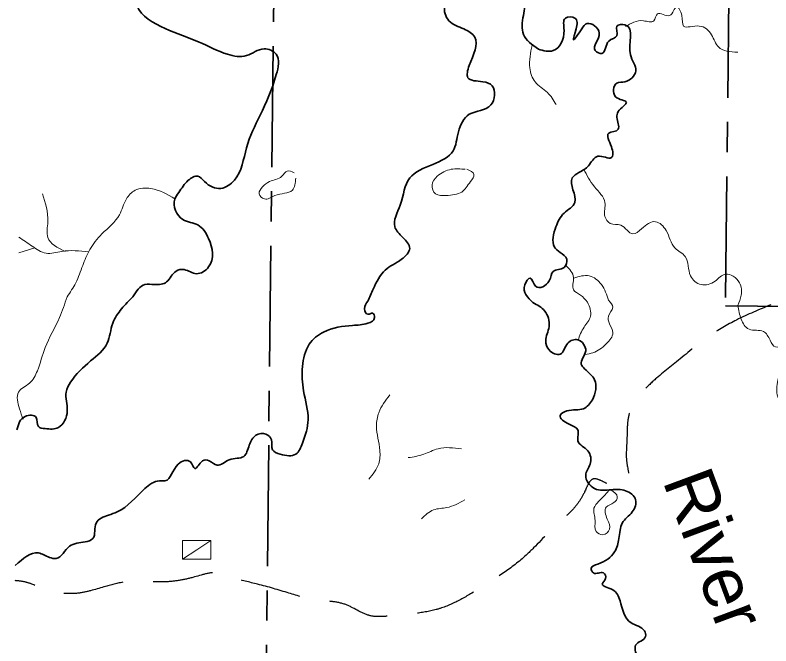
# Model space of a CAD drawing. Extents: x 796677 to 815278, y 8501144 to 8534586.
# Drawn here: x 796696 to 799695, y 8504527 to 8507030 of the extents above; entities that cross this region are included whole.
import ezdxf

# ---------------------------------------------------------------- set-up
doc = ezdxf.new("R2010")
doc.units = 0
doc.header["$LTSCALE"] = 80
doc.linetypes.add('LONG_DASH_SHORT_DASH', pattern=[9.9, 6, -1.2, 1.5, -1.2])
doc.linetypes.add('MEDIUM_DASHED', pattern=[4.5, 3, -1.5])
for name, color, linetype, lineweight in [('15', 7, 'Continuous', 13), ('3', 7, 'Continuous', 13), ('6', 7, 'MEDIUM_DASHED', 25), ('62', 7, 'LONG_DASH_SHORT_DASH', 35)]:
    doc.layers.add(name, color=color, linetype=linetype, lineweight=lineweight)

msp = doc.modelspace()

# ---------------------------------------------------------------- linework, layer by layer
at = {"layer": '15'}
msp.add_line((796774.85, 8506106.01), (796710.95, 8506086.47), dxfattribs=at)
at = {"layer": '15', "lineweight": 35}
for points in [[(797262.63, 8511826.29), (797300.24, 8511772.54), (797332.47, 8511595.13), (797348.58, 8511545.67), (797402.3, 8511481.16), (797418.41, 8511422.03), (797450.64, 8511373.64), (797466.76, 8511298.38), (797423.79, 8511250), (797407.67, 8511223.12), (797439.9, 8511147.86), (797472.13, 8511094.1), (797472.13, 8511024.21), (797482.87, 8510970.45), (797525.85, 8510948.95), (797590.31, 8510954.32), (797617.17, 8510922.07), (797558.08, 8510862.93), (797541.96, 8510819.93), (797547.33, 8510739.29), (797563.45, 8510674.78), (797547.33, 8510615.64), (797509.73, 8510578.01), (797525.85, 8510508.13), (797574.19, 8510448.99), (797568.82, 8510384.48), (797568.82, 8510330.72), (797590.31, 8510276.96), (797563.45, 8510217.83), (797531.22, 8510180.2), (797531.22, 8510121.06), (797558.08, 8510067.3), (797547.33, 8509975.91), (797579.57, 8509895.27), (797670.88, 8509836.14), (797729.97, 8509777), (797713.86, 8509626.48), (797692.37, 8509572.72), (797660.14, 8509535.09), (797633.28, 8509481.33), (797627.91, 8509422.19), (797676.26, 8509416.82), (797762.2, 8509373.81), (797815.92, 8509357.68), (797848.15, 8509282.42), (797923.36, 8509250.17), (797971.7, 8509217.91), (798036.16, 8509244.79), (798095.25, 8509212.53), (798122.11, 8509142.65), (798213.43, 8509137.27), (798245.66, 8509115.77), (798240.29, 8509040.51), (798240.29, 8508975.99), (798294, 8508916.86), (798320.86, 8508836.22), (798294, 8508793.21), (798245.66, 8508749.13), (798224.17, 8508711.5), (798234.92, 8508657.74), (798304.75, 8508598.61), (798331.61, 8508528.72), (798347.72, 8508426.58), (798363.84, 8508383.57), (798390.69, 8508329.81), (798374.58, 8508313.68), (798331.61, 8508319.06), (798294, 8508286.81), (798299.38, 8508211.54), (798277.89, 8508163.16), (798261.77, 8508125.53), (798304.75, 8508098.65), (798336.98, 8508061.02), (798294, 8508012.63), (798218.8, 8507926.62), (798191.94, 8507845.98), (798197.31, 8507776.09), (798267.15, 8507722.34), (798358.46, 8507684.7), (798412.18, 8507604.07), (798487.39, 8507555.68), (798557.22, 8507453.54), (798589.45, 8507410.53), (798600.19, 8507324.52), (798600.19, 8507276.14), (798637.79, 8507249.26), (798632.42, 8507157.87), (798713, 8507093.36), (798713, 8507028.85), (798713, 8506953.58), (798772.09, 8506894.45)], [(797628.32, 8509421.78), (797571.51, 8509391.55), (797490.94, 8509391.55), (797464.08, 8509418.43), (797421.1, 8509413.06), (797362.01, 8509396.93), (797319.04, 8509402.31), (797308.3, 8509327.04), (797324.41, 8509267.91), (797286.81, 8509224.9), (797243.84, 8509106.63), (797211.61, 8509020.62), (797184.75, 8508961.48), (797157.89, 8508918.48), (797163.26, 8508886.22), (797233.09, 8508864.72), (797254.58, 8508800.21), (797259.95, 8508751.82), (797302.93, 8508698.06), (797324.41, 8508601.3), (797335.16, 8508569.04), (797383.5, 8508569.04), (797421.1, 8508579.79), (797453.33, 8508552.91), (797464.08, 8508488.4), (797480.19, 8508445.4), (797480.19, 8508375.51), (797431.85, 8508375.51), (797415.73, 8508321.75), (797394.24, 8508262.62), (797313.67, 8508198.11), (797249.21, 8508138.97), (797216.98, 8508047.58), (797195.49, 8507977.69), (797141.77, 8507945.44), (797136.4, 8507864.8), (797179.38, 8507773.41), (797184.75, 8507687.39), (797184.75, 8507617.51), (797206.23, 8507558.37), (797211.61, 8507483.11), (797200.86, 8507440.1), (797200.86, 8507386.34), (797157.89, 8507386.34), (797098.8, 8507375.59), (797088.06, 8507284.2), (797093.43, 8507257.32), (797147.15, 8507202.49), (797179.38, 8507068.09), (797292.18, 8506976.7), (797426.48, 8506922.94), (797539.28, 8506874.56), (797614.49, 8506869.18), (797684.32, 8506896.06), (797732.66, 8506874.56), (797732.66, 8506793.92), (797668.2, 8506632.64), (797614.49, 8506503.62), (797566.14, 8506374.6), (797512.42, 8506342.35), (797447.96, 8506369.23), (797421.1, 8506390.73), (797383.5, 8506374.6), (797345.9, 8506326.22), (797329.78, 8506299.34), (797362.01, 8506218.7), (797421.1, 8506197.2), (797464.08, 8506143.44), (797464.08, 8506030.54), (797415.73, 8506003.66), (797367.39, 8506019.79), (797335.16, 8506014.42), (797297.55, 8505971.41), (797249.21, 8505960.66), (797211.61, 8505960.66), (797163.26, 8505912.27)], [(798591.86, 8507405.46), (798530.36, 8507340.65), (798476.64, 8507313.77), (798439.04, 8507297.64), (798433.67, 8507270.76), (798476.64, 8507238.51), (798476.64, 8507190.12), (798449.78, 8507120.24), (798401.44, 8507066.48), (798417.55, 8507007.34), (798476.64, 8506975.09), (798519.62, 8506942.83), (798498.13, 8506829.94), (798492.76, 8506781.55), (798551.85, 8506765.43), (798589.45, 8506749.3), (798584.08, 8506674.04), (798498.13, 8506636.4), (798455.16, 8506566.52), (798433.67, 8506491.26), (798353.09, 8506437.5), (798261.77, 8506383.74), (798224.17, 8506276.22), (798202.68, 8506190.21), (798234.92, 8506147.2), (798261.77, 8506104.19), (798229.54, 8506061.18), (798165.08, 8506018.18), (798116.74, 8505942.91), (798095.25, 8505894.53)], [(798772.09, 8506894.45), (798831.18, 8506889.07), (798874.15, 8506969.71), (798879.52, 8507018.09), (798917.12, 8507018.09), (798922.5, 8506975.09), (798911.75, 8506932.08), (798943.98, 8506975.09), (798965.47, 8506996.59), (799013.81, 8506958.96), (798997.7, 8506889.07), (799024.56, 8506878.32), (799051.42, 8506926.7), (799083.65, 8506948.21), (799083.65, 8506985.84), (799115.88, 8506991.21), (799137.36, 8506872.94), (799158.85, 8506808.43), (799115.88, 8506765.43), (799083.65, 8506760.05), (799078.28, 8506706.29), (799121.25, 8506684.79), (799089.02, 8506647.16), (799089.02, 8506598.77), (799089.02, 8506577.27), (799051.42, 8506561.14), (799062.16, 8506507.38), (799062.16, 8506464.38), (799008.44, 8506469.75), (798970.84, 8506432.12), (798933.24, 8506405.24), (798906.38, 8506383.74), (798917.12, 8506286.97), (798874.15, 8506243.96), (798841.92, 8506190.21), (798836.55, 8506109.57), (798858.03, 8506088.06), (798884.89, 8506061.18), (798874.15, 8506028.93), (798831.18, 8506012.8), (798815.06, 8505975.17), (798761.34, 8505953.67), (798739.86, 8505985.92), (798718.37, 8505959.04), (798750.6, 8505889.15)], [(796703.15, 8505384.49), (796736.23, 8505437.27), (796780.24, 8505432.87), (796789.05, 8505397.63), (796815.46, 8505388.82), (796868.27, 8505393.22), (796903.49, 8505459.3), (796899.09, 8505534.18), (796916.69, 8505573.83), (796995.92, 8505657.52), (797061.94, 8505728), (797083.95, 8505807.29), (797119.16, 8505864.56), (797163.26, 8505912.27)], [(796697.15, 8504845.45), (796789.05, 8504895.46), (796833.06, 8504877.84), (796859.47, 8504873.43), (796912.29, 8504921.89), (796973.91, 8504939.51), (797004.72, 8504952.72), (797017.93, 8505014.39), (797066.34, 8505045.23), (797101.56, 8505058.44), (797211.6, 8505150.95), (797268.82, 8505181.78), (797290.82, 8505181.78), (797343.64, 8505247.86), (797392.06, 8505256.67), (797409.66, 8505230.24), (797440.48, 8505261.07), (797466.88, 8505261.07), (797497.7, 8505243.45), (797546.11, 8505265.48), (797603.33, 8505278.69), (797625.34, 8505322.74), (797651.75, 8505362.39), (797691.36, 8505366.79), (797713.37, 8505344.77), (797717.77, 8505305.12), (797748.58, 8505287.5), (797810.2, 8505287.5), (797836.61, 8505331.55), (797858.62, 8505424.06), (797841.02, 8505538.59), (797836.61, 8505635.5), (797863.02, 8505723.6), (797920.24, 8505772.05), (798034.68, 8505798.48), (798096.31, 8505807.29), (798122.71, 8505829.32), (798113.91, 8505846.94), (798096.31, 8505842.53), (798083.1, 8505864.56), (798095.25, 8505894.53)], [(798750.6, 8505889.15), (798797.03, 8505855.75), (798814.64, 8505794.08), (798801.43, 8505736.81), (798814.64, 8505701.57), (798858.65, 8505683.95), (798889.47, 8505728), (798929.08, 8505741.22), (798959.89, 8505697.17), (798942.28, 8505644.31), (798955.49, 8505626.69), (798995.1, 8505582.64), (798986.3, 8505503.35), (798951.09, 8505468.11), (798885.06, 8505459.3), (798858.65, 8505441.68), (798893.87, 8505406.44), (798929.08, 8505384.41), (798929.08, 8505340.36), (798968.69, 8505300.72), (798977.5, 8505247.86), (798959.89, 8505203.81), (798995.1, 8505150.95), (799061.13, 8505146.54), (799118.35, 8505142.14), (799157.96, 8505106.9), (799144.75, 8505058.44), (799105.14, 8505014.39), (799091.94, 8504952.72), (799074.33, 8504899.86), (799008.31, 8504851.41), (798981.9, 8504833.79), (798990.7, 8504816.17), (799030.31, 8504816.17), (799039.12, 8504794.14), (799025.91, 8504772.12), (799065.53, 8504750.09), (799096.34, 8504706.04), (799140.35, 8504617.94), (799193.17, 8504586.22), (799197.57, 8504564.2), (799157.96, 8504528.96), (799157.96, 8504502.53), (799179.97, 8504462.88), (799228.38, 8504462.88), (799268, 8504462.88), (799285.6, 8504440.86), (799263.6, 8504414.43), (799210.78, 8504392.4), (799193.17, 8504370.38), (799215.18, 8504326.33), (799250.39, 8504308.71), (799294.41, 8504326.33), (799320.82, 8504370.38), (799369.23, 8504370.38), (799378.04, 8504321.92), (799369.23, 8504225.01), (799351.63, 8504154.53), (799369.23, 8504119.29), (799413.25, 8504084.05), (799452.86, 8504053.22), (799444.06, 8504004.76), (799404.45, 8503978.33), (799382.44, 8503912.26), (799386.84, 8503890.23), (799435.26, 8503881.42), (799452.86, 8503854.99), (799439.66, 8503819.75), (799400.04, 8503793.32), (799422.05, 8503766.89), (799470.47, 8503784.51), (799483.67, 8503731.65), (799466.07, 8503683.2), (799483.67, 8503643.55), (799540.89, 8503621.53), (799593.71, 8503639.15), (799628.92, 8503630.34), (799633.33, 8503608.31), (799589.31, 8503586.29), (799598.11, 8503551.05), (799633.33, 8503511.4), (799672.94, 8503511.4), (799699.35, 8503449.73), (799703.75, 8503388.06), (799672.94, 8503339.61), (799681.74, 8503304.37), (799734.56, 8503304.37), (799782.98, 8503321.99), (799831.4, 8503295.56), (799862.21, 8503282.34), (799919.43, 8503313.18)]]:
    msp.add_spline(points, degree=3, dxfattribs=at)
at = {"layer": '15'}
for points in [[(799117.77, 8506984.41), (799188.87, 8507007.49), (799230.44, 8507007.49), (799244.3, 8507035.22), (799292.8, 8507028.29), (799320.52, 8507062.96), (799341.3, 8507028.29), (799348.23, 8506986.69), (799410.59, 8506986.69), (799459.09, 8506952.02), (799486.81, 8506903.48), (799563.02, 8506882.68)], [(798747.05, 8506909.88), (798738.51, 8506820.28), (798759.29, 8506764.81), (798807.79, 8506723.21), (798842.44, 8506674.67)], [(798482.15, 8506418.13), (798426.72, 8506418.13), (798371.29, 8506390.39), (798350.5, 8506355.72), (798364.36, 8506321.06), (798405.93, 8506314.12), (798468.29, 8506327.99), (798502.93, 8506369.59), (798516.79, 8506397.33), (798489.08, 8506418.13)], [(798952.06, 8506418.69), (798994.87, 8506348.79), (799036.44, 8506286.39), (799036.44, 8506230.92), (799057.23, 8506203.18), (799098.8, 8506196.25), (799147.3, 8506161.58), (799181.94, 8506182.38), (799237.37, 8506210.12), (799278.94, 8506175.45), (799313.59, 8506106.11), (799355.16, 8506071.44), (799375.95, 8505995.17), (799417.52, 8505960.51), (799472.95, 8505974.37), (799514.52, 8506002.11), (799569.95, 8505967.44), (799576.88, 8505918.9), (799563.02, 8505877.3)], [(797810.06, 8506383.46), (797796.21, 8506334.92), (797726.92, 8506314.12), (797685.35, 8506300.25), (797664.56, 8506321.06), (797678.42, 8506348.79), (797706.13, 8506369.59), (797754.64, 8506390.39), (797775.42, 8506411.19), (797803.14, 8506404.26)], [(797330.66, 8506301.26), (797234.98, 8506341.86), (797172.63, 8506334.92), (797137.98, 8506300.25), (797110.27, 8506237.85), (797040.98, 8506161.58), (796992.48, 8506099.18), (796964.77, 8506036.78), (796937.05, 8505967.44), (796902.41, 8505911.97)], [(796895.65, 8506092.08), (796826.19, 8506147.71), (796826.19, 8506210.12), (796805.41, 8506321.06)], [(796988.17, 8506090.93), (796881.62, 8506092.25), (796819.26, 8506085.31), (796763.83, 8506113.05), (796711.64, 8506148.73)], [(798880.75, 8506037.02), (798911.72, 8505988.24), (798911.72, 8505939.71), (798939.44, 8505918.9), (798967.15, 8505891.17)], [(798912.76, 8505986.26), (798974.08, 8505995.17), (799022.58, 8505960.51), (799050.3, 8505898.1)], [(796902.41, 8505911.97), (796872.68, 8505829.32), (796815.46, 8505710.38), (796784.65, 8505617.88), (796753.83, 8505569.42), (796709.82, 8505534.18), (796714.22, 8505468.11), (796727.87, 8505426.24)], [(798967.15, 8505891.17), (798979.65, 8505835.4), (798953.24, 8505791.35), (798929.71, 8505740.77)], [(799050.3, 8505898.1), (799067.68, 8505870.64), (799050.07, 8505835.4), (799054.48, 8505804.56), (799067.68, 8505769.32), (799041.27, 8505725.27), (798988.45, 8505690.03), (798957.94, 8505683.24)], [(799563.02, 8505877.3), (799576.99, 8505823.15), (799607.8, 8505783.5), (799665.02, 8505774.69), (799691.43, 8505739.45), (799713.44, 8505713.02), (799739.85, 8505713.02), (799748.65, 8505664.57), (799722.24, 8505580.87), (799722.24, 8505514.8), (799775.06, 8505448.72), (799797.07, 8505413.48), (799797.07, 8505378.24), (799823.48, 8505351.81), (799845.49, 8505320.98), (799841.09, 8505224.07), (799836.68, 8505153.59), (799805.87, 8505105.13), (799814.68, 8505052.27), (799885.1, 8505008.22), (799937.92, 8504990.6), (799995.14, 8504920.12), (800012.75, 8504884.88), (800069.97, 8504876.07), (800131.59, 8504871.67), (800210.81, 8504862.86), (800241.63, 8504801.19), (800237.22, 8504726.3), (800180, 8504655.82), (800127.19, 8504629.39), (800118.38, 8504589.75), (800166.8, 8504497.24), (800210.81, 8504391.52), (800285.64, 8504316.64), (800364.87, 8504254.97), (800448.5, 8504210.92), (800501.32, 8504171.27), (800598.15, 8504114.01), (800694.98, 8504114.01), (800756.61, 8504122.82), (800813.83, 8504184.49), (800840.24, 8504232.94), (800919.46, 8504246.16), (800985.49, 8504290.21), (801011.9, 8504395.93), (801060.31, 8504470.81), (801104.33, 8504514.86), (801143.94, 8504594.15), (801179.15, 8504673.44), (801249.58, 8504717.49), (801311.2, 8504730.71), (801377.22, 8504717.49), (801469.66, 8504655.82), (801553.29, 8504602.96), (801632.51, 8504528.08), (801672.13, 8504466.41), (801729.35, 8504404.74), (801755.76, 8504365.09)], [(798182.97, 8505522.64), (798138.96, 8505452.16), (798130.15, 8505399.3), (798143.36, 8505302.39), (798138.96, 8505249.53), (798099.34, 8505187.86)], [(798466.87, 8505309), (798374.44, 8505309), (798317.22, 8505286.97), (798255.6, 8505273.76)], [(799059.37, 8505146.66), (799085.29, 8505117.38), (799072.08, 8505095.36), (799041.27, 8505077.74), (799045.67, 8505029.28), (799054.48, 8504989.64), (799028.07, 8504967.61), (799001.66, 8504980.83), (798997.26, 8505024.88), (798992.85, 8505073.33), (799010.46, 8505099.76), (799036.87, 8505126.19), (799054.92, 8505146.95)], [(798480.08, 8505106.37), (798409.65, 8505075.53), (798356.83, 8505066.72), (798308.42, 8505031.48)]]:
    msp.add_spline(points, degree=3, dxfattribs=at)
at = {"layer": '3'}
for p in [(797472.99, 8504945.5), (797360.49, 8504870.5)]:
    msp.add_line(p, (797416.74, 8504908), dxfattribs=at)
msp.add_lwpolyline([(797360.49, 8504870.5), (797472.99, 8504870.5), (797472.99, 8504945.5), (797360.49, 8504945.5)], close=True, dxfattribs=at)
at = {"layer": '6'}
msp.add_spline([(799694.6, 8505880.53), (799558.34, 8505819.98), (799451.81, 8505757.79), (799327.52, 8505660.06), (799220.99, 8505571.22), (799132.22, 8505446.83), (799123.34, 8505340.22), (799123.34, 8505251.37), (799123.34, 8505180.3), (799087.83, 8505162.53), (799043.44, 8505171.41), (798990.18, 8505189.18), (798954.67, 8505135.87), (798839.26, 8505002.6), (798723.85, 8504887.11), (798537.42, 8504753.84), (798377.62, 8504673.88), (798200.07, 8504647.22), (798102.42, 8504647.22), (798004.76, 8504691.64), (797889.36, 8504709.41), (797782.83, 8504736.07), (797658.54, 8504771.61), (797560.89, 8504798.26), (797507.62, 8504816.03), (797401.09, 8504798.26), (797285.68, 8504780.49), (797134.76, 8504780.49), (797054.86, 8504762.72), (796948.33, 8504736.07), (796806.29, 8504753.84), (796735.27, 8504780.49), (796696.49, 8504785.66)], degree=3, dxfattribs=at)
at = {"layer": '62'}
msp.add_lwpolyline([(798016.61, 8533572.26), (814284.25, 8533388.27), (814262.81, 8531543), (808840.42, 8531605.49), (808819.33, 8529760.28), (810626.64, 8529739.55), (810605.4, 8527894.32), (806991.04, 8527935.71), (807012.04, 8529780.9), (805204.77, 8529801.39), (805225.62, 8531646.54), (803418.25, 8531666.89), (803356, 8526131.49), (801549.03, 8526151.78), (801424.6, 8515081.06), (799618.4, 8515101.38), (799514.64, 8505875.84), (801320.21, 8505855.41), (801278.28, 8502165.14), (799472.96, 8502185.61), (799493.81, 8504030.73), (797688.38, 8504051.06), (798016.61, 8533572.26)], close=True, dxfattribs=at)

# ---------------------------------------------------------------- texts
at = {"layer": '15', "width": 1.05}
msp.add_text('River', height=200, rotation=290.37, dxfattribs=at).set_placement((799263.57, 8505182.67))

doc.saveas('drawing.dxf')
